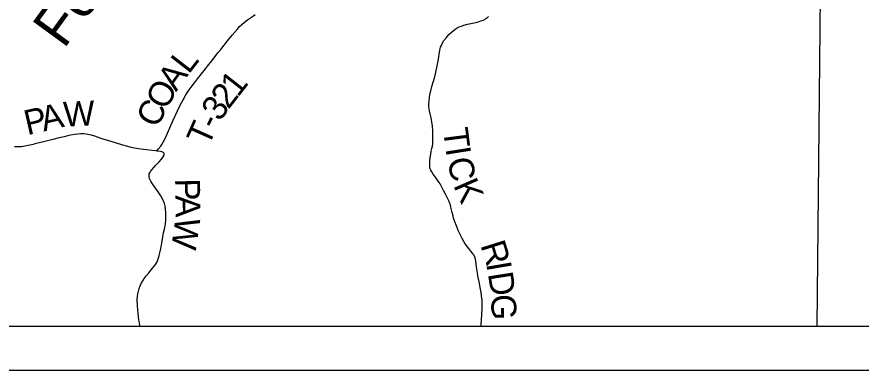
# Model space of a CAD drawing. Extents: x -10 to 158, y 8 to 33.
# Drawn here: x 128.609 to 130.537, y 24.962 to 25.769 of the extents above; entities that cross this region are included whole.
import ezdxf

# ---------------------------------------------------------------- set-up
doc = ezdxf.new("R2010")
doc.units = 0
for name, color, linetype in [('GM_X_Major_River_Text', 7, 'Continuous'), ('GM_X_Township_Road', 7, 'Continuous'), ('GM_X_Township_Road_Text', 7, 'Continuous'), ('GM_X_Township_Text', 7, 'Continuous'), ('SH_Data', 7, 'Continuous'), ('SH_Text', 7, 'Continuous')]:
    doc.layers.add(name, color=color, linetype=linetype)

msp = doc.modelspace()

# ---------------------------------------------------------------- linework, layer by layer
at = {"layer": 'GM_X_Township_Road'}
for points in [[(128.9286, 25.4624), (128.9322, 25.4669), (128.9378, 25.4736), (128.9406, 25.4777), (128.9437, 25.483), (128.9479, 25.4913), (128.9533, 25.5032), (128.9662, 25.5328), (128.9761, 25.5543), (128.9833, 25.5687), (128.9892, 25.5797), (128.9955, 25.5904), (129.0008, 25.5988), (129.0077, 25.6084), (129.0151, 25.6183), (129.0243, 25.63), (129.0255, 25.6315), (129.0282, 25.6349), (129.0401, 25.65), (129.0447, 25.6559), (129.0572, 25.6721), (129.0591, 25.6745), (129.062, 25.6785), (129.0659, 25.6833), (129.0689, 25.6873), (129.0747, 25.6944), (129.0902, 25.7138), (129.1011, 25.7273), (129.112, 25.7401), (129.1179, 25.7464), (129.1233, 25.7516), (129.1294, 25.7569), (129.1362, 25.7622), (129.1448, 25.7683), (129.1535, 25.7744)], [(129.6468, 25.2331), (129.6461, 25.2339), (129.6412, 25.2402), (129.6356, 25.2476), (129.631, 25.2541), (129.6281, 25.2588), (129.626, 25.2625), (129.6229, 25.2686), (129.618, 25.2793), (129.6131, 25.2914), (129.6096, 25.3007), (129.6067, 25.3095), (129.6053, 25.3142), (129.6033, 25.322), (129.6006, 25.334), (129.5992, 25.3393), (129.598, 25.3429), (129.5964, 25.3469), (129.5925, 25.3546), (129.5878, 25.3641), (129.5836, 25.3724), (129.5792, 25.3813), (129.5758, 25.3872), (129.5717, 25.3935), (129.5651, 25.4025), (129.5596, 25.41), (129.5566, 25.4147), (129.5547, 25.4186), (129.5534, 25.422), (129.5526, 25.4256), (129.5522, 25.4293), (129.5521, 25.4336), (129.5521, 25.4396), (129.5529, 25.4475), (129.5543, 25.4555), (129.5557, 25.4618), (129.557, 25.468), (129.5581, 25.4733), (129.5588, 25.479), (129.5593, 25.4856), (129.5593, 25.4952), (129.5591, 25.5077), (129.5582, 25.5199), (129.5572, 25.5282), (129.5564, 25.5344), (129.5555, 25.5382), (129.554, 25.544), (129.5517, 25.5539), (129.5507, 25.5587), (129.5502, 25.5631), (129.5501, 25.5686), (129.5505, 25.5761), (129.5514, 25.5841), (129.5526, 25.5921), (129.5544, 25.5999), (129.5572, 25.6101), (129.5601, 25.6196), (129.5638, 25.6321), (129.5654, 25.6387), (129.5692, 25.657), (129.5722, 25.6722), (129.5732, 25.6777), (129.5739, 25.6833), (129.575, 25.6919), (129.5759, 25.6962), (129.577, 25.6997), (129.5786, 25.7031), (129.5808, 25.7081), (129.5846, 25.7144), (129.5902, 25.722), (129.5959, 25.7281), (129.6012, 25.7331), (129.6058, 25.7372), (129.6103, 25.7405), (129.6149, 25.7434), (129.6193, 25.7456), (129.6245, 25.7478), (129.6301, 25.7497), (129.638, 25.7517), (129.65, 25.7542), (129.6608, 25.757), (129.6691, 25.7594), (129.6743, 25.7614), (129.6777, 25.763), (129.6803, 25.7647), (129.6833, 25.7669), (129.6864, 25.7699)], [(128.9286, 25.4624), (128.9256, 25.4628), (128.9176, 25.4639), (128.9058, 25.4652), (128.8984, 25.466), (128.8874, 25.4675), (128.8776, 25.4692), (128.8703, 25.4707), (128.8624, 25.4726), (128.8511, 25.4757), (128.8344, 25.4808), (128.819, 25.4856), (128.8066, 25.4896), (128.7995, 25.492), (128.7872, 25.4962), (128.78, 25.4983), (128.775, 25.4995), (128.7673, 25.5009), (128.7617, 25.5015), (128.7555, 25.5016), (128.7487, 25.5011), (128.7419, 25.5002), (128.7315, 25.4983), (128.723, 25.4964), (128.717, 25.4949), (128.7062, 25.4923), (128.6911, 25.4885), (128.6827, 25.4864), (128.67, 25.4833), (128.6507, 25.4787), (128.6464, 25.4777), (128.6392, 25.4761), (128.6276, 25.4736), (128.6196, 25.4724), (128.6153, 25.472), (128.6103, 25.4719), (128.6041, 25.4724)], [(128.8908, 25.0623), (128.8902, 25.0644), (128.889, 25.0699), (128.8879, 25.0766), (128.8862, 25.0927), (128.8855, 25.1001), (128.8848, 25.1093), (128.8845, 25.113), (128.8844, 25.118), (128.8844, 25.1236), (128.8848, 25.1304), (128.8854, 25.1366), (128.8867, 25.1426), (128.8885, 25.1486), (128.8907, 25.1544), (128.8933, 25.16), (128.8966, 25.166), (128.9003, 25.1718), (128.9043, 25.1773), (128.9103, 25.1844), (128.9192, 25.1948), (128.9242, 25.2011), (128.9274, 25.2058), (128.9295, 25.2093), (128.9315, 25.2141), (128.933, 25.2188), (128.9342, 25.2236), (128.935, 25.2272), (128.9364, 25.2333), (128.9379, 25.2399), (128.9388, 25.2442), (128.9395, 25.2478), (128.9405, 25.2527), (128.9413, 25.2569), (128.9428, 25.2666), (128.9444, 25.2755), (128.9461, 25.2844), (128.9484, 25.2961), (128.9493, 25.3056), (128.9497, 25.315), (128.9495, 25.3225), (128.9488, 25.3299), (128.9477, 25.3363), (128.9461, 25.3424), (128.9424, 25.3519), (128.9381, 25.3601), (128.9321, 25.369), (128.9257, 25.3776), (128.9188, 25.3872), (128.915, 25.3938), (128.9124, 25.4), (128.9117, 25.4032), (128.9115, 25.4071), (128.9118, 25.4103), (128.9126, 25.4127), (128.9146, 25.4158), (128.9168, 25.4187), (128.9219, 25.4247), (128.9262, 25.4291), (128.9299, 25.4331), (128.9339, 25.4376), (128.9397, 25.4442), (128.9435, 25.4491), (128.9457, 25.4531), (128.946, 25.4559), (128.9457, 25.457), (128.945, 25.4581), (128.9437, 25.4594), (128.9427, 25.46), (128.9403, 25.4608), (128.9373, 25.4613), (128.9286, 25.4624)], [(129.6691, 25.0623), (129.6692, 25.0641), (129.6695, 25.0672), (129.6697, 25.0702), (129.67, 25.0745), (129.6703, 25.0794), (129.6707, 25.0868), (129.6714, 25.0942), (129.6715, 25.0992), (129.6716, 25.1159), (129.6715, 25.1215), (129.6711, 25.1265), (129.6706, 25.132), (129.6694, 25.14), (129.668, 25.1473), (129.6646, 25.1637), (129.6618, 25.1778), (129.6608, 25.1833), (129.6596, 25.1925), (129.6577, 25.2104), (129.6567, 25.2159), (129.6552, 25.2199), (129.6534, 25.2239), (129.6524, 25.2255), (129.6507, 25.228), (129.6468, 25.2331)]]:
    msp.add_lwpolyline(points, dxfattribs=at)
at = {"layer": 'GM_X_Township_Text'}
msp.add_lwpolyline([(130.461, 27.8534), (130.4499, 27.7117), (130.4527, 27.3822), (130.46, 27.1989), (130.4491, 26.3467), (130.4362, 25.0623), (132.9038, 25.0623), (132.9038, 27.8123)], dxfattribs=at)
at = {"layer": 'SH_Data'}
for p, q in [((126.1038, 25.0623), (132.9038, 25.0623)), ((126.0038, 24.9623), (133.0038, 24.9623))]:
    msp.add_line(p, q, dxfattribs=at)
at = {"layer": 'SH_Text'}
msp.add_lwpolyline([(126.1038, 27.0364), (126.1038, 25.0623), (130.4362, 25.0623)], dxfattribs=at)

# ---------------------------------------------------------------- texts
at = {"layer": 'GM_X_Major_River_Text'}
msp.add_text('Fork', height=0.09473, rotation=53.9104, dxfattribs=at).set_placement((128.7167, 25.6937))
at = {"layer": 'GM_X_Township_Road_Text'}
for s, rotation, p in [('L', 52.1307, (129.0016, 25.6364)), ('A', 54.395, (128.9729, 25.5963)), ('1', 51.9904, (129.114, 25.5837)), ('O', 62.0501, (128.9505, 25.5538)), ('2', 52.1798, (129.0925, 25.5561)), ('3', 55.4569, (129.0732, 25.528)), ('P', 13.0658, (128.6332, 25.4983)), ('A', 12.9733, (128.6705, 25.5069)), ('W', 2.7289, (128.7166, 25.5178)), ('C', 62.6774, (128.9292, 25.5125)), ('T', 65.9426, (129.0468, 25.4707)), ('-', 63.3616, (129.0638, 25.5089)), ('T', 277.2664, (129.5823, 25.5123)), ('I', 279.0725, (129.5879, 25.4682)), ('C', 281.3138, (129.592, 25.4428)), ('P', 271.131, (128.9706, 25.3994)), ('K', 293.5754, (129.6052, 25.3844)), ('A', 270.5756, (128.9714, 25.3613)), ('W', 261.7854, (128.972, 25.3136)), ('R', 287.4043, (129.6673, 25.2478)), ('I', 279.6946, (129.6808, 25.2053)), ('D', 278.9024, (129.6847, 25.1825)), ('G', 271.2059, (129.6923, 25.1351))]:
    msp.add_text(s, height=0.0568, rotation=rotation, dxfattribs=at).set_placement(p)

doc.saveas('drawing.dxf')
